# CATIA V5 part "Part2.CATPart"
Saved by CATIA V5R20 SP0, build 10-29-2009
Part number: 盖子
Bounding box of the stored display mesh (mm): x 0 to 5, y -23.984 to 44.814, z -19.949 to 19.949
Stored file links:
  D:\CATIA Data\Part2.CATPart
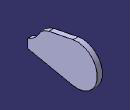
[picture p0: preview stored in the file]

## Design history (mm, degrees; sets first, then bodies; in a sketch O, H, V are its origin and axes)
Body1 (main body)
  Sketch1 on yz-plane, origin (0, 0, 0), H (0, 1, 0), V (0, 0, 1)
    arc A1 centre (0, 0) radius 15 from (-3, 14.6969) to (-12.973, 7.5301) ccw
    arc A2 centre (25, 0) radius 20 from (21, -19.5959) to (21, 19.5959) ccw
    point P1 (25, 0)
    line L1 (21, -19.5959) -> (-3, -14.6969)
    line L2 (21, 19.5959) -> (-3, 14.6969)
    arc A3 centre (-32, 18.5742) radius 22 from (-23.9842, -1.9136) to (-12.973, 7.5301) ccw
    point P6 (-32, 18.5742)
    line L3 (-3, -14.6969) -> (-23.9842, -10.4136)
    line L4 (-23.9842, -10.4136) -> (-23.9842, -1.9136)
    radius A1 = 15
    distance O P1 = 25
    radius A2 = 20
    radius A3 = 22
    distance P6 V = 32
    length L4 = 8.5
    coincidence: P1 H, L3 L1
    tangency: L1 A1, L1 A2, L2 A1, L2 A2, A3 A1, L3 A1
    vertical: L4 V
  Pad1: profile Sketch1, direction (1, 0, 0), length 5
  Shell1: IntOffset 1, Face start face of Pad1, ExtOffset 0
  Sketch2 on face of Shell1, origin (4, 0, 0), H (0, -1, 0), V (0, 0, 1)
    circle A1 centre (0, 0) radius 1.5
    radius A1 = 1.5
  Pad2: profile Sketch2, direction (-1, 0, 0), length 1
  Sketch3 on end face of Pad2, origin (3, 0, 0), H (0, 1, 0), V (0, 0, -1)
    point P1 (0, 0)
  Hole1: placed by Sketch3, at (3, 0, 0) direction (1, 0, 0), diameter 2, depth 1
  Sketch4 on face of Shell1, origin (4, 0, 0), H (0, -1, 0), V (0, 0, 1)
    axis line L1 (0, 0) -> (-20, 40)
    circle A1 centre (-6.9318, 13.8636) radius 1
    point P2 (-6.9318, 13.8636)
    radius A1 = 1
    distance P2 O = 15.5
    angle L1 H = 116.5651
    coincidence: P2 L1
  Pad3: profile Sketch4, direction (-1, 0, 0), length 4
  Sketch5 on end face of Pad3, origin (0, 6.9318, 13.8636), H (0, 1, 0), V (0, 0, -1)
    point P1 (0, 0)
  Hole2: placed by Sketch5, at (0, 6.9318, 13.8636) direction (1, 0, 0), diameter 1, depth 2
  Sketch6 on face of Shell1, origin (4, 0, 0), H (0, -1, 0), V (0, 0, 1)
    axis line L1 (0, 0) -> (-20, -40)
    circle A1 centre (-6.9318, -13.8636) radius 1
    point P2 (-6.9318, -13.8636)
    radius A1 = 1
    distance O P2 = 15.5
    angle L1 H = 116.5651
    coincidence: P2 L1
  Pad4: profile Sketch6, direction (-1, 0, 0), length 4
  Sketch7 on end face of Pad4, origin (0, 6.9318, -13.8636), H (0, 1, 0), V (0, 0, -1)
    point P1 (0, 0)
  Hole3: placed by Sketch7, at (0, 6.9318, -13.8636) direction (1, 0, 0), diameter 1, depth 2
  Sketch8 on face of Shell1, origin (4, 0, 0), H (0, -1, 0), V (0, 0, 1)
    circle A1 centre (-42, 0) radius 1
    point P1 (-42, 0)
    radius A1 = 1
    distance P1 O = 42
    coincidence: P1 H
  Pad5: profile Sketch8, direction (-1, 0, 0), length 4
  Sketch9 on end face of Pad5, origin (0, 42, 0), H (0, 1, 0), V (0, 0, -1)
    point P1 (0, 0)
  Hole4: placed by Sketch9, at (0, 42, 0) direction (1, 0, 0), diameter 1, depth 2
  Body2
    Sketch10 on face of Pad1 from Sketch1.L4, origin (0, -23.9842, 0), H (1, 0, 0), V (0, 0, 1)
      line L1 (0, -3.4566) -> (3, -3.4566)
      line L2 (3, -3.4566) -> (3, -8.4566)
      line L3 (3, -8.4566) -> (0, -8.4566)
      line L4 (0, -8.4566) -> (0, -3.4566)
      reference projected line E1 (0, -1.9136) -> (0, -10.4136) from edge [start face of Pad1 | face of Pad1 from Sketch1.L4]
      reference projected line E2 (0, -1.9136) -> (5, -1.9136) from edge [face of Pad1 from Sketch1.L4 | face of Pad1 from Sketch1.A3]
      length L1 = 3
      length L2 = 5
      distance E2 L1 = 1.543
      horizontal: L1 H, L3 H
      vertical: L2 V, L4 V
      coincidence: E1 L4
    Pad6: profile Sketch10, direction (0, 1, 0), length 1
  Remove1: tool Body2
  Sketch11 on face of Shell1, origin (4, 0, 0), H (0, -1, 0), V (0, 0, 1)
    circle A1 centre (15.5, -5.5) radius 1.5
    point P1 (15.5, -5.5)
    radius A1 = 1.5
    distance P1 V = 15.5
    distance H P1 = 5.5
  Pad7: profile Sketch11, direction (-1, 0, 0), length 1
  Sketch12 on end face of Pad7, origin (3, -15.5, -5.5), H (0, 1, 0), V (0, 0, -1)
    point P1 (0, 0)
  Hole5: placed by Sketch12, at (3, -15.5, -5.5) direction (1, 0, 0), diameter 2, depth 1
